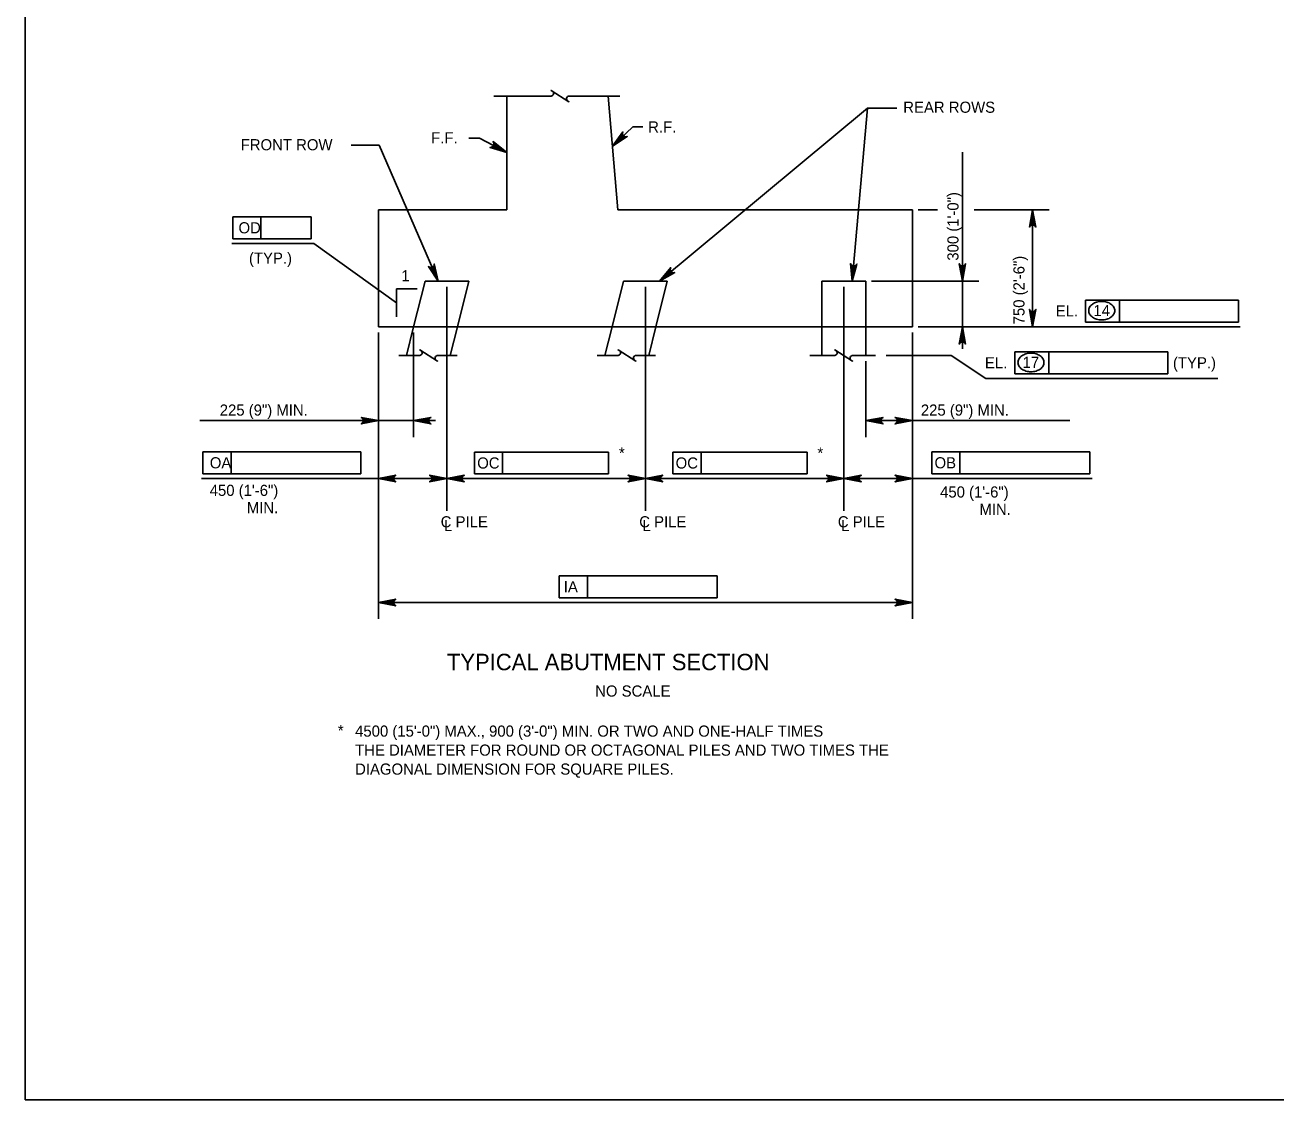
# Model space of a CAD drawing. Extents: x 638340 to 640241, y 295465 to 298435.
# Drawn here: x 639316.5 to 639653.4, y 296074.5 to 296364 of the extents above; entities that cross this region are included whole.
import ezdxf

# ---------------------------------------------------------------- set-up
doc = ezdxf.new("R2010")
doc.units = 0
for name, color, linetype in [('2', 7, 'Continuous'), ('4', 7, 'Continuous'), ('5', 7, 'Continuous')]:
    doc.layers.add(name, color=color, linetype=linetype)

msp = doc.modelspace()

# ---------------------------------------------------------------- linework, layer by layer
at = {"layer": '2'}
for p, q in [((639316.46, 296074.46), (639316.46, 296638.46)), ((639543.39, 296341.58), (639551.33, 296341.58)), ((639474.7, 296331.34), (639480.16, 296336.5)), ((639480.16, 296336.5), (639482.9, 296336.5)), ((639438.9, 296333.45), (639436.04, 296333.45)), ((639446.25, 296329.64), (639438.9, 296333.45)), ((639411.85, 296331.57), (639404.33, 296331.57)), ((639568.96, 296294.99), (639568.96, 296329.69)), ((639557.03, 296314.19), (639562.25, 296314.19)), ((639572.12, 296314.19), (639592.31, 296314.19)), ((639587.88, 296314.19), (639587.88, 296282.69)), ((639372.45, 296312.3), (639393.58, 296312.3)), ((639372.45, 296312.3), (639372.45, 296306.39)), ((639380.01, 296312.3), (639380.01, 296306.39)), ((639393.58, 296312.3), (639393.58, 296306.39)), ((639372.45, 296306.39), (639393.58, 296306.39)), ((639394.28, 296305.12), (639372.16, 296305.12)), ((639416.51, 296289.16), (639394.28, 296305.12)), ((639416.51, 296292.91), (639416.51, 296285.41)), ((639422.06, 296292.91), (639416.51, 296292.91)), ((639430.11, 296293.45), (639430.11, 296233.12)), ((639430.11, 296293.45), (639430.11, 296233.12)), ((639483.56, 296293.45), (639483.56, 296233.12)), ((639537.04, 296293.45), (639537.04, 296233.12)), ((639544.48, 296294.99), (639573.39, 296294.99)), ((639568.96, 296294.99), (639568.96, 296282.69)), ((639602.12, 296289.88), (639643.33, 296289.88)), ((639602.12, 296283.97), (639602.12, 296289.88)), ((639611.29, 296283.97), (639611.29, 296289.88)), ((639643.33, 296289.88), (639643.33, 296283.97)), ((639557.03, 296282.69), (639643.8, 296282.69)), ((639557.03, 296282.69), (639573.39, 296282.69)), ((639568.96, 296282.69), (639568.96, 296276.79)), ((639643.33, 296283.97), (639602.12, 296283.97)), ((639411.68, 296281.15), (639411.68, 296204.02)), ((639411.68, 296281.15), (639411.68, 296253)), ((639411.68, 296281.15), (639411.68, 296228.76)), ((639421.13, 296281.15), (639421.13, 296253)), ((639555.49, 296281.15), (639555.49, 296204.02)), ((639555.49, 296281.15), (639555.49, 296253)), ((639555.49, 296281.15), (639555.49, 296228.76)), ((639583.05, 296275.93), (639624.26, 296275.93)), ((639583.05, 296270.02), (639583.05, 296275.93)), ((639592.22, 296270.02), (639592.22, 296275.93)), ((639624.26, 296275.93), (639624.26, 296270.02)), ((639542.94, 296273.42), (639542.94, 296253)), ((639548.44, 296274.96), (639565.9, 296274.96)), ((639565.9, 296274.96), (639575.25, 296268.74)), ((639575.25, 296268.74), (639637.8, 296268.74)), ((639624.26, 296270.02), (639583.05, 296270.02)), ((639421.13, 296257.43), (639363.58, 296257.43)), ((639421.13, 296257.43), (639427.04, 296257.43)), ((639542.94, 296257.43), (639555.49, 296257.43)), ((639555.49, 296257.43), (639597.94, 296257.43)), ((639364.39, 296249.01), (639406.92, 296249.01)), ((639364.39, 296249.01), (639364.39, 296243.1)), ((639371.96, 296249.01), (639371.96, 296243.1)), ((639406.92, 296249.01), (639406.92, 296243.1)), ((639437.54, 296248.96), (639473.67, 296248.96)), ((639437.54, 296248.96), (639437.54, 296243.06)), ((639445.1, 296248.96), (639445.1, 296243.06)), ((639473.67, 296248.96), (639473.67, 296243.06)), ((639490.99, 296248.96), (639527.12, 296248.96)), ((639490.99, 296248.96), (639490.99, 296243.06)), ((639498.55, 296248.96), (639498.55, 296243.06)), ((639527.12, 296248.96), (639527.12, 296243.06)), ((639555.49, 296250.35), (639555.49, 296230.23)), ((639560.72, 296249.01), (639603.25, 296249.01)), ((639560.72, 296249.01), (639560.72, 296243.1)), ((639568.29, 296249.01), (639568.29, 296243.1)), ((639603.25, 296249.01), (639603.25, 296243.1)), ((639430.11, 296238.8), (639430.11, 296246.25)), ((639483.56, 296238.8), (639483.56, 296246.25)), ((639411.68, 296241.83), (639363.98, 296241.83)), ((639364.39, 296243.1), (639406.92, 296243.1)), ((639427.16, 296241.83), (639411.68, 296241.83)), ((639433.07, 296241.83), (639480.61, 296241.83)), ((639437.54, 296243.06), (639473.67, 296243.06)), ((639486.51, 296241.83), (639534.06, 296241.83)), ((639490.99, 296243.06), (639527.12, 296243.06)), ((639539.99, 296241.83), (639555.49, 296241.83)), ((639555.49, 296241.83), (639603.89, 296241.83)), ((639560.72, 296243.1), (639603.25, 296243.1)), ((639460.37, 296215.63), (639502.89, 296215.63)), ((639460.37, 296215.63), (639460.37, 296209.72)), ((639467.93, 296215.63), (639467.93, 296209.72)), ((639502.89, 296215.63), (639502.89, 296209.72)), ((639411.68, 296208.45), (639555.49, 296208.45)), ((639460.37, 296209.72), (639502.89, 296209.72)), ((640102.46, 296074.46), (639316.46, 296074.46))]:
    msp.add_line(p, q, dxfattribs=at)
for points in [[(639487.35, 296294.99), (639543.39, 296341.58)], [(639539.27, 296294.99), (639543.39, 296341.58)], [(639474.7, 296331.34), (639477.49, 296335.17), (639477.4, 296334.74), (639477.47, 296334.39), (639477.65, 296334.13), (639477.9, 296333.94), (639478.25, 296333.84), (639478.69, 296333.9), (639474.7, 296331.34), (639478.25, 296333.84), (639477.9, 296333.94), (639474.7, 296331.34), (639477.65, 296334.13), (639477.47, 296334.39), (639474.7, 296331.34), (639477.4, 296334.74)], [(639427.77, 296294.99), (639411.85, 296331.57)], [(639446.25, 296329.64), (639441.71, 296331.01), (639442.15, 296331.07), (639442.45, 296331.26), (639442.65, 296331.51), (639442.74, 296331.81), (639442.72, 296332.18), (639442.52, 296332.56), (639446.25, 296329.64), (639442.72, 296332.18), (639442.74, 296331.81), (639446.25, 296329.64), (639442.65, 296331.51), (639442.45, 296331.26), (639446.25, 296329.64), (639442.15, 296331.07)], [(639587.88, 296314.19), (639588.75, 296309.53), (639588.5, 296309.89), (639588.19, 296310.07), (639587.88, 296310.13), (639587.56, 296310.07), (639587.25, 296309.89), (639587, 296309.53), (639587.88, 296314.19), (639587.25, 296309.89), (639587.56, 296310.07), (639587.88, 296314.19), (639587.88, 296310.13), (639588.19, 296310.07), (639587.88, 296314.19), (639588.5, 296309.89)], [(639427.77, 296294.99), (639425.11, 296298.92), (639425.48, 296298.68), (639425.84, 296298.64), (639426.15, 296298.72), (639426.42, 296298.89), (639426.63, 296299.18), (639426.71, 296299.61), (639427.77, 296294.99), (639426.63, 296299.18), (639426.42, 296298.89), (639427.77, 296294.99), (639426.15, 296298.72), (639425.84, 296298.64), (639427.77, 296294.99), (639425.48, 296298.68)], [(639539.27, 296294.99), (639538.81, 296299.71), (639539.02, 296299.33), (639539.32, 296299.12), (639539.62, 296299.04), (639539.94, 296299.06), (639540.27, 296299.22), (639540.55, 296299.56), (639539.27, 296294.99), (639540.27, 296299.22), (639539.94, 296299.06), (639539.27, 296294.99), (639539.62, 296299.04), (639539.32, 296299.12), (639539.27, 296294.99), (639539.02, 296299.33)], [(639568.96, 296294.99), (639568.09, 296299.65), (639568.33, 296299.29), (639568.65, 296299.11), (639568.96, 296299.05), (639569.27, 296299.11), (639569.58, 296299.29), (639569.83, 296299.65), (639568.96, 296294.99), (639569.58, 296299.29), (639569.27, 296299.11), (639568.96, 296294.99), (639568.96, 296299.05), (639568.65, 296299.11), (639568.96, 296294.99), (639568.33, 296299.29)], [(639487.35, 296294.99), (639490.38, 296298.64), (639490.26, 296298.22), (639490.32, 296297.86), (639490.48, 296297.59), (639490.72, 296297.38), (639491.06, 296297.26), (639491.49, 296297.3), (639487.35, 296294.99), (639491.06, 296297.26), (639490.72, 296297.38), (639487.35, 296294.99), (639490.48, 296297.59), (639490.32, 296297.86), (639487.35, 296294.99), (639490.26, 296298.22)], [(639587.88, 296282.69), (639587, 296287.35), (639587.25, 296286.99), (639587.56, 296286.81), (639587.88, 296286.75), (639588.19, 296286.81), (639588.5, 296286.99), (639588.75, 296287.35), (639587.88, 296282.69), (639588.5, 296286.99), (639588.19, 296286.81), (639587.88, 296282.69), (639587.88, 296286.75), (639587.56, 296286.81), (639587.88, 296282.69), (639587.25, 296286.99)], [(639568.96, 296282.69), (639569.83, 296278.03), (639569.58, 296278.39), (639569.27, 296278.57), (639568.96, 296278.63), (639568.65, 296278.57), (639568.33, 296278.39), (639568.09, 296278.03), (639568.96, 296282.69), (639568.33, 296278.39), (639568.65, 296278.57), (639568.96, 296282.69), (639568.96, 296278.63), (639569.27, 296278.57), (639568.96, 296282.69), (639569.58, 296278.39)], [(639411.68, 296257.43), (639407.02, 296256.55), (639407.38, 296256.8), (639407.57, 296257.11), (639407.62, 296257.43), (639407.57, 296257.74), (639407.38, 296258.05), (639407.02, 296258.3), (639411.68, 296257.43), (639407.38, 296258.05), (639407.57, 296257.74), (639411.68, 296257.43), (639407.62, 296257.43), (639407.57, 296257.11), (639411.68, 296257.43), (639407.38, 296256.8)], [(639421.13, 296257.43), (639425.8, 296258.3), (639425.44, 296258.05), (639425.25, 296257.74), (639425.2, 296257.43), (639425.25, 296257.11), (639425.44, 296256.8), (639425.8, 296256.55), (639421.13, 296257.43), (639425.44, 296256.8), (639425.25, 296257.11), (639421.13, 296257.43), (639425.2, 296257.43), (639425.25, 296257.74), (639421.13, 296257.43), (639425.44, 296258.05)], [(639542.94, 296257.43), (639547.6, 296258.3), (639547.24, 296258.05), (639547.06, 296257.74), (639547.01, 296257.43), (639547.06, 296257.11), (639547.24, 296256.8), (639547.6, 296256.55), (639542.94, 296257.43), (639547.24, 296256.8), (639547.06, 296257.11), (639542.94, 296257.43), (639547.01, 296257.43), (639547.06, 296257.74), (639542.94, 296257.43), (639547.24, 296258.05)], [(639555.49, 296257.43), (639550.83, 296256.55), (639551.19, 296256.8), (639551.37, 296257.11), (639551.43, 296257.43), (639551.37, 296257.74), (639551.19, 296258.05), (639550.83, 296258.3), (639555.49, 296257.43), (639551.19, 296258.05), (639551.37, 296257.74), (639555.49, 296257.43), (639551.43, 296257.43), (639551.37, 296257.11), (639555.49, 296257.43), (639551.19, 296256.8)], [(639411.68, 296241.83), (639416.34, 296242.7), (639415.99, 296242.45), (639415.8, 296242.14), (639415.75, 296241.83), (639415.8, 296241.51), (639415.99, 296241.2), (639416.34, 296240.95), (639411.68, 296241.83), (639415.99, 296241.2), (639415.8, 296241.51), (639411.68, 296241.83), (639415.75, 296241.83), (639415.8, 296242.14), (639411.68, 296241.83), (639415.99, 296242.45)], [(639430.11, 296241.83), (639425.45, 296240.95), (639425.81, 296241.2), (639426, 296241.51), (639426.05, 296241.83), (639426, 296242.14), (639425.81, 296242.45), (639425.45, 296242.7), (639430.11, 296241.83), (639425.81, 296242.45), (639426, 296242.14), (639430.11, 296241.83), (639426.05, 296241.83), (639426, 296241.51), (639430.11, 296241.83), (639425.81, 296241.2)], [(639430.11, 296241.83), (639434.77, 296240.95), (639434.42, 296241.2), (639434.23, 296241.51), (639434.18, 296241.83), (639434.23, 296242.14), (639434.42, 296242.45), (639434.77, 296242.7), (639430.11, 296241.83), (639434.42, 296242.45), (639434.23, 296242.14), (639430.11, 296241.83), (639434.18, 296241.83), (639434.23, 296241.51), (639430.11, 296241.83), (639434.42, 296241.2)], [(639483.56, 296241.83), (639478.9, 296240.95), (639479.26, 296241.2), (639479.45, 296241.51), (639479.5, 296241.83), (639479.45, 296242.14), (639479.26, 296242.45), (639478.9, 296242.7), (639483.56, 296241.83), (639479.26, 296242.45), (639479.45, 296242.14), (639483.56, 296241.83), (639479.5, 296241.83), (639479.45, 296241.51), (639483.56, 296241.83), (639479.26, 296241.2)], [(639483.56, 296241.83), (639488.22, 296240.95), (639487.86, 296241.2), (639487.68, 296241.51), (639487.63, 296241.83), (639487.68, 296242.14), (639487.86, 296242.45), (639488.22, 296242.7), (639483.56, 296241.83), (639487.86, 296242.45), (639487.68, 296242.14), (639483.56, 296241.83), (639487.63, 296241.83), (639487.68, 296241.51), (639483.56, 296241.83), (639487.86, 296241.2)], [(639537.04, 296241.83), (639532.38, 296240.95), (639532.73, 296241.2), (639532.92, 296241.51), (639532.97, 296241.83), (639532.92, 296242.14), (639532.73, 296242.45), (639532.38, 296242.7), (639537.04, 296241.83), (639532.73, 296242.45), (639532.92, 296242.14), (639537.04, 296241.83), (639532.97, 296241.83), (639532.92, 296241.51), (639537.04, 296241.83), (639532.73, 296241.2)], [(639537.04, 296241.83), (639541.7, 296240.95), (639541.34, 296241.2), (639541.15, 296241.51), (639541.1, 296241.83), (639541.15, 296242.14), (639541.34, 296242.45), (639541.7, 296242.7), (639537.04, 296241.83), (639541.34, 296242.45), (639541.15, 296242.14), (639537.04, 296241.83), (639541.1, 296241.83), (639541.15, 296241.51), (639537.04, 296241.83), (639541.34, 296241.2)], [(639555.49, 296241.83), (639550.83, 296240.95), (639551.19, 296241.2), (639551.37, 296241.51), (639551.43, 296241.83), (639551.37, 296242.14), (639551.19, 296242.45), (639550.83, 296242.7), (639555.49, 296241.83), (639551.19, 296242.45), (639551.37, 296242.14), (639555.49, 296241.83), (639551.43, 296241.83), (639551.37, 296241.51), (639555.49, 296241.83), (639551.19, 296241.2)], [(639411.68, 296208.45), (639416.34, 296209.32), (639415.99, 296209.07), (639415.8, 296208.76), (639415.75, 296208.45), (639415.8, 296208.13), (639415.99, 296207.82), (639416.34, 296207.57), (639411.68, 296208.45), (639415.99, 296207.82), (639415.8, 296208.13), (639411.68, 296208.45), (639415.75, 296208.45), (639415.8, 296208.76), (639411.68, 296208.45), (639415.99, 296209.07)], [(639555.49, 296208.45), (639550.83, 296207.57), (639551.19, 296207.82), (639551.37, 296208.13), (639551.43, 296208.45), (639551.37, 296208.76), (639551.19, 296209.07), (639550.83, 296209.32), (639555.49, 296208.45), (639551.19, 296209.07), (639551.37, 296208.76), (639555.49, 296208.45), (639551.43, 296208.45), (639551.37, 296208.13), (639555.49, 296208.45), (639551.19, 296207.82)]]:
    msp.add_lwpolyline(points, dxfattribs=at)
for points in [[(639477.18, 296333.01), (639476.51, 296333.72), (639474.7, 296331.34)], [(639443.86, 296331.44), (639443.4, 296330.56), (639446.25, 296329.64)], [(639587.38, 296311.24), (639588.37, 296311.24), (639587.88, 296314.19)], [(639427.77, 296294.99), (639426.82, 296297.8), (639426.37, 296297.6)], [(639487.35, 296294.99), (639489.78, 296296.69), (639489.46, 296297.07)], [(639539.27, 296294.99), (639539.59, 296297.94), (639539.09, 296297.95)], [(639568.47, 296297.94), (639569.45, 296297.94), (639568.96, 296294.99)], [(639587.38, 296285.65), (639588.37, 296285.65), (639587.88, 296282.69)], [(639568.47, 296279.74), (639569.45, 296279.74), (639568.96, 296282.69)], [(639408.73, 296257.92), (639408.73, 296256.93), (639411.68, 296257.43)], [(639424.09, 296257.92), (639424.09, 296256.93), (639421.13, 296257.43)], [(639545.89, 296257.92), (639545.89, 296256.93), (639542.94, 296257.43)], [(639552.54, 296257.92), (639552.54, 296256.93), (639555.49, 296257.43)], [(639427.16, 296242.32), (639427.16, 296241.33), (639430.11, 296241.83)], [(639433.07, 296242.32), (639433.07, 296241.33), (639430.11, 296241.83)], [(639480.61, 296242.32), (639480.61, 296241.33), (639483.56, 296241.83)], [(639486.51, 296242.32), (639486.51, 296241.33), (639483.56, 296241.83)], [(639534.06, 296242.32), (639534.06, 296241.33), (639537.01, 296241.83)], [(639539.99, 296242.32), (639539.99, 296241.33), (639537.04, 296241.83)], [(639552.54, 296242.32), (639552.54, 296241.33), (639555.49, 296241.83)], [(639414.64, 296208.94), (639414.64, 296207.95), (639411.68, 296208.45)], [(639552.54, 296208.94), (639552.54, 296207.95), (639555.49, 296208.45)]]:
    msp.add_lwpolyline(points, close=True, dxfattribs=at)
for centre, radius, start, end in [((639606.15, 296285.83), 3.66, 106.5358, 125.6316), ((639606.49, 296284.67), 4.87, 90, 106.5358), ((639606.49, 296284.67), 4.87, 73.4642, 90), ((639606.84, 296285.83), 3.66, 54.3684, 73.4642), ((639604.82, 296287.03), 1.83, 149.9767, 180), ((639604.82, 296287.03), 1.83, 180, 210.0233), ((639605.62, 296286.57), 2.76, 125.6316, 149.9767), ((639605.62, 296287.5), 2.76, 210.0233, 234.3684), ((639607.37, 296286.57), 2.76, 30.0233, 54.3684), ((639607.37, 296287.5), 2.76, 305.6316, 329.9767), ((639608.17, 296287.03), 1.83, 0, 30.0233), ((639608.17, 296287.03), 1.83, 329.9767, 0), ((639606.15, 296288.23), 3.66, 234.3684, 253.4642), ((639606.49, 296289.39), 4.87, 253.4642, 270), ((639606.49, 296289.39), 4.87, 270, 286.5358), ((639606.84, 296288.23), 3.66, 286.5358, 305.6316), ((639587.42, 296270.72), 4.87, 90, 106.5358), ((639587.42, 296270.72), 4.87, 73.4642, 90), ((639585.75, 296273.08), 1.83, 149.9767, 180), ((639585.75, 296273.08), 1.83, 180, 210.0233), ((639586.55, 296272.61), 2.76, 125.6316, 149.9767), ((639586.55, 296273.55), 2.76, 210.0233, 234.3684), ((639587.08, 296271.88), 3.66, 106.5358, 125.6316), ((639587.77, 296271.88), 3.66, 54.3684, 73.4642), ((639588.3, 296272.61), 2.76, 30.0233, 54.3684), ((639588.3, 296273.55), 2.76, 305.6316, 329.9767), ((639589.1, 296273.08), 1.83, 0, 30.0233), ((639589.1, 296273.08), 1.83, 329.9767, 0), ((639587.08, 296274.28), 3.66, 234.3684, 253.4642), ((639587.42, 296275.44), 4.87, 253.4642, 270), ((639587.42, 296275.44), 4.87, 270, 286.5358), ((639587.77, 296274.28), 3.66, 286.5358, 305.6316)]:
    msp.add_arc(centre, radius, start, end, dxfattribs=at)
at = {"layer": '4'}
for p, q in [((639458.18, 296344.82), (639442.73, 296344.82)), ((639446.25, 296314.19), (639446.25, 296344.82)), ((639476.72, 296344.82), (639463.04, 296344.82)), ((639473.57, 296344.82), (639476.13, 296314.19)), ((639411.68, 296314.19), (639411.68, 296282.69)), ((639446.25, 296314.19), (639411.68, 296314.19)), ((639555.49, 296314.19), (639476.13, 296314.19)), ((639555.49, 296282.69), (639555.49, 296314.19)), ((639555.49, 296282.69), (639411.68, 296282.69))]:
    msp.add_line(p, q, dxfattribs=at)
msp.add_lwpolyline([(639462.68, 296343.49), (639462.98, 296343.31), (639458.17, 296346.33), (639458.49, 296346.13)], dxfattribs=at)
for centre, start, end in [((639458.12, 296345.53), 275.3286, 57.8672), ((639463.04, 296344.11), 90, 240)]:
    msp.add_arc(centre, 0.71, start, end, dxfattribs=at)
at = {"layer": '5'}
for p, q in [((639421.13, 296282.69), (639424.21, 296294.99)), ((639436.02, 296294.99), (639424.21, 296294.99)), ((639432.95, 296282.69), (639436.02, 296294.99)), ((639474.58, 296282.69), (639477.66, 296294.99)), ((639489.47, 296294.99), (639477.66, 296294.99)), ((639486.39, 296282.69), (639489.47, 296294.99)), ((639531.13, 296282.69), (639531.13, 296294.99)), ((639542.94, 296294.99), (639531.13, 296294.99)), ((639542.94, 296282.69), (639542.94, 296294.99)), ((639419.2, 296274.96), (639421.13, 296282.69)), ((639431.01, 296274.96), (639432.95, 296282.69)), ((639472.65, 296274.96), (639474.58, 296282.69)), ((639484.46, 296274.96), (639486.39, 296282.69)), ((639531.13, 296274.96), (639531.13, 296282.69)), ((639542.94, 296274.96), (639542.94, 296282.69)), ((639422.78, 296274.96), (639417.17, 296274.96)), ((639432.82, 296274.96), (639427.63, 296274.96)), ((639476.22, 296274.96), (639470.62, 296274.96)), ((639486.27, 296274.96), (639481.08, 296274.96)), ((639534.57, 296274.96), (639527.84, 296274.96)), ((639545.57, 296274.96), (639539.42, 296274.96))]:
    msp.add_line(p, q, dxfattribs=at)
for points in [[(639427.28, 296273.63), (639427.58, 296273.45), (639422.77, 296276.47), (639423.09, 296276.27)], [(639480.72, 296273.63), (639481.02, 296273.45), (639476.21, 296276.47), (639476.54, 296276.27)], [(639539.07, 296273.63), (639539.37, 296273.45), (639534.56, 296276.47), (639534.88, 296276.27)]]:
    msp.add_lwpolyline(points, dxfattribs=at)
for centre, start, end in [((639422.71, 296275.67), 275.3286, 57.8672), ((639476.16, 296275.67), 275.3286, 57.8672), ((639534.5, 296275.67), 275.3286, 57.8672), ((639427.63, 296274.25), 90, 240), ((639481.08, 296274.25), 90, 240), ((639539.42, 296274.25), 90, 240)]:
    msp.add_arc(centre, 0.71, start, end, dxfattribs=at)

# ---------------------------------------------------------------- texts
at = {"layer": '2'}
for s, height, p in [('REAR ROWS', 3, (639553.03, 296340.32)), ('R.F.', 3, (639484.31, 296335.01)), ('FRONT ROW', 3, (639374.55, 296330.22)), ('F.F.', 3, (639425.86, 296332.09)), ('1', 3, (639417.84, 296294.95)), ('EL.', 3, (639594.1, 296285.46)), ('14', 3, (639604.25, 296285.57)), ('EL.', 3, (639575.03, 296271.5)), ('17', 3, (639585.17, 296271.62)), ('(TYP.)', 3, (639625.67, 296271.5)), ('225 (9") MIN.', 3.0001, (639368.91, 296258.76)), ('225 (9") MIN.', 3.0001, (639557.77, 296258.76)), ('450 (1\'-6")', 3.0001, (639366.2, 296237.14)), ('450 (1\'-6")', 3.0001, (639562.95, 296236.7)), ('MIN.', 3, (639376.2, 296232.48)), ('MIN.', 3, (639573.54, 296232.04)), ('C PILE', 3, (639428.42, 296228.67)), ('C PILE', 3, (639481.91, 296228.67)), ('C PILE', 3, (639535.4, 296228.67)), ('L', 3, (639429.31, 296227.65)), ('L', 3, (639482.8, 296227.65)), ('L', 3, (639536.29, 296227.65)), ('NO SCALE', 3, (639470.04, 296183.09)), ('4500 (15\'-0") MAX., 900 (3\'-0") MIN. OR TWO AND ONE-HALF TIMES', 3.0001, (639405.37, 296172.3)), ('THE DIAMETER FOR ROUND OR OCTAGONAL PILES AND TWO TIMES THE', 3.0001, (639405.37, 296167.18)), ('DIAGONAL DIMENSION FOR SQUARE PILES.', 3.0001, (639405.37, 296162.07))]:
    msp.add_text(s, height=height, dxfattribs=at).set_placement(p)
for s, height, rotation, p in [('300 (1\'-0")', 3.0001, 90, (639567.91, 296300.49)), ('OD', 3, 359.9382, (639373.96, 296307.85)), ('(TYP.)', 3, 359.9382, (639376.78, 296299.69)), ('750 (2\'-6")', 3.0001, 90, (639585.69, 296283.34)), ('*', 3, 359.9382, (639476.45, 296247.19)), ('*', 3, 359.9382, (639529.9, 296247.19)), ('OA', 3, 359.9382, (639366.23, 296244.56)), ('OC', 3, 359.9382, (639438.26, 296244.51)), ('OC', 3, 359.9382, (639491.71, 296244.51)), ('OB', 3, 359.9382, (639561.45, 296244.56)), ('IA', 3, 359.9382, (639461.58, 296211.18)), ('*', 3, 359.9382, (639400.72, 296172.46))]:
    msp.add_text(s, height=height, rotation=rotation, dxfattribs=at).set_placement(p)
at = {"layer": '4'}
msp.add_text('TYPICAL ABUTMENT SECTION', height=4.4294, dxfattribs=at).set_placement((639430.11, 296190.19))

doc.saveas('drawing.dxf')
